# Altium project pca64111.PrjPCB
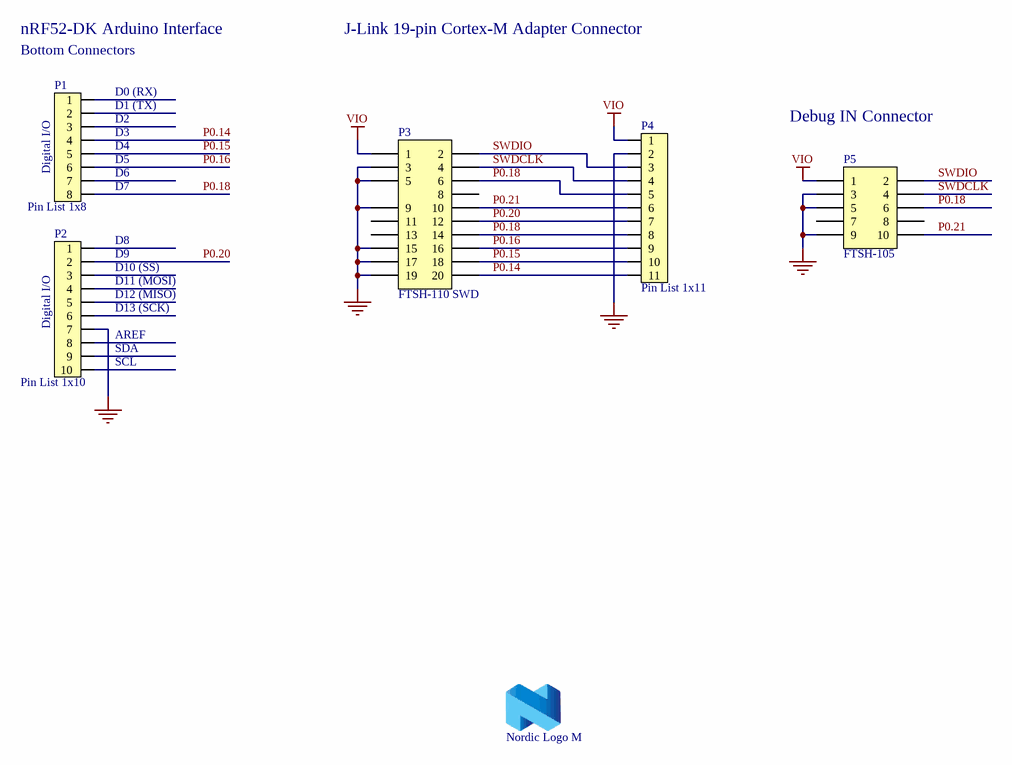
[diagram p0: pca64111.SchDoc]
1 sheet, 6 parts. Net scope: global (net labels, ports and power ports of the same name join across sheets).
Board file: 400178.PcbDoc

## Sheet pca64111.SchDoc: ETM shield for nRF52-DK
size A4; Revision: 0.1.0; SheetNumber: 1; SheetTotal: 1; DrawnBy: KJP; ProjectNumber: 4397; PCBRevision: 0070KJP; DocumentSize: A4; PCAName: PCA64111; PCBNumber: 400178

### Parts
LOGO1  Nordic Logo M  [NORDIC_LOGO_M]  (no BOM)
P1  Pin List 1x8  [LIST_1x8_SMD]
P2  Pin List 1x10  [LIST_1x10_SMD]
P3  FTSH-110 SWD  [FTSH-110-K-SWD]
P4  Pin List 1x11  [LIST_1x11_SMD]
P5  FTSH-105  [FTSH-105-K]

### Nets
GND: P2.7 P3.3 P3.5 P3.9 P3.15 P3.17 P3.19 P4.2 P5.3 P5.5 P5.9
VIO: P3.1 P4.1 P5.1
P0.14: P1.4 P3.20 P4.11
P0.15: P1.5 P3.18 P4.10
P0.16: P1.6 P3.16 P4.9
P0.18: P1.8 P3.6 P3.14 P4.5 P4.8 P5.6
P0.20: P2.2 P3.12 P4.7
P0.21: P3.10 P4.6 P5.10
SWDCLK: P3.4 P4.4 P5.4
SWDIO: P3.2 P4.3 P5.2

Not connected (* = marked no-connect by the designer): P1 1 2 3 7; P2 1 3 4 5 6 8 9 10; P3 8 11 13; P5 7 8

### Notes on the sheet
- nRF52-DK Arduino Interface
- (near P1) Bottom Connectors
- J-Link 19-pin Cortex-M Adapter Connector
- (near P1) D0 (RX)
- (near P1) D1 (TX)
- (near P1) D2
- (near P1) D3
- (near P1) D4
- Debug IN Connector
- (near P1) Digital I/O
- (near P1) D5
- (near P1) D6
- (near P1) D7
- D8
- (near P2) D9
- (near P2) D10 (SS)
- (near P2) D11 (MOSI)
- (near P2) Digital I/O
- (near P2) AREF
- (near P2) D12 (MISO)
- (near P2) D13 (SCK)
- (near P2) SDA
- (near P2) SCL

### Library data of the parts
LOGO1 = Nordic Logo M: Nordic Logo, medium size; Artikkelnr Noca: N.A.
P1 = Pin List 1x8 SMD: Pin List 1x8, 2.54mm (100mil), SMD; Artikkelnr Noca: 55019253; Artikkelnr Simpro: N.A.
P2 = Pin List 1x10 SMD: Pin List 1x10, 2.54mm (100mil), SMD; Artikkelnr Noca: 55019254; Artikkelnr Simpro: N.A.
P3 = Samtec FTSH-110 SWD Keying Shroud: SAMTEC - CONN HEADER 20POS DUAL .05" SMD KEYING SHROUD Removed Pin 7; Manufacturer Part Number: FTSH-110-01-F-DV-K; Note: HEADER, 1.27MM, SMD, 20WAY, Keying Shroud Removed Pin 7; Artikkelnr Noca: N.A.
P4 = Pin List 1x11 SMD: Pin List 1x11, 2.54mm (100mil), SMD; Artikkelnr Noca: N.A.
P5 = Samtec FTSH-105 Keying Shroud: SAMTEC - CONN HEADER 10POS DUAL .05" SMD KEYING SHROUD; Manufacturer Part Number: FTSH-105-01-F-DV-K; Note: HEADER, 1.27MM, SMD, 10WAY, Keying Shroud; Artikkelnr Noca: N.A.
